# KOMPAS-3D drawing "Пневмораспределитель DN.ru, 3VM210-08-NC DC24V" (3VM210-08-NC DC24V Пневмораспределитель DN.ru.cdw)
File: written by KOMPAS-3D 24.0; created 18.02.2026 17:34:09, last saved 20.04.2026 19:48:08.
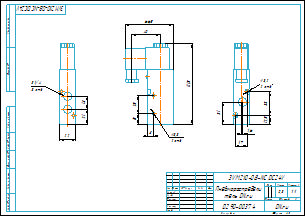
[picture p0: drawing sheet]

Document properties: Автор: R2D2; Форматы листов документа: A3; Полное имя файла: 3VM210-08-NC DC24V Пневмораспределитель DN.ru.m3d; Масса: 0.3; Наименование: Пневмораспределитель DN.ru; Количество листов документа: 1; Примечание: D290-00374

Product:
- Part/product: Пневмораспределитель DN.ru  | designation 3VM210-08-NC DC24V
    Масса: 0.3
    Раздел спецификации: Прочие изделия
    Примечание: D290-00374

Views: Вид 1, Спереди, Проекционный вид 2, Проекционный вид 3
Referenced files in E:\Работа\Зайцев\Аксессуары для пневмоприводов\Пневмораспределители DN.ru\3VM210-06-NC Пневмораспределитель DN.RU\AC24V\: 3VM210-06-NC AC24V Пневмораспределитель DN.ru.m3d
Referenced files in E:\Работа\Зайцев\Аксессуары для пневмоприводов\Пневмораспределители DN.ru\3VM210-08-NC Пневмораспределитель DN.RU\DC24V\: 3VM210-08-NC DC24V Пневмораспределитель DN.ru.m3d
Referenced files in E:\Работа\Зайцев\Для компаса\: чертеж DN.ru А3.cdt
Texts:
  чертеж DN.ru А3.cdt
  Пневмораспредели
  тель DN.ru
  Пневмораспределитель DN.ru
  3VM210-08-NC DC24V Пневмораспределитель DN.ru
Dimensions and other numbers on the sheet: 0; 3; 2; 4; 3 отв.; 21; 18; 22; 3VM210-08-NC DC24V; 66,5; 40; 111,5; 3,3; 2 отв.; 15; 25; 8; 9; 3,2; 33; 12,5; 17; 1,6; 31; 6; 1:1; 1; 0,3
